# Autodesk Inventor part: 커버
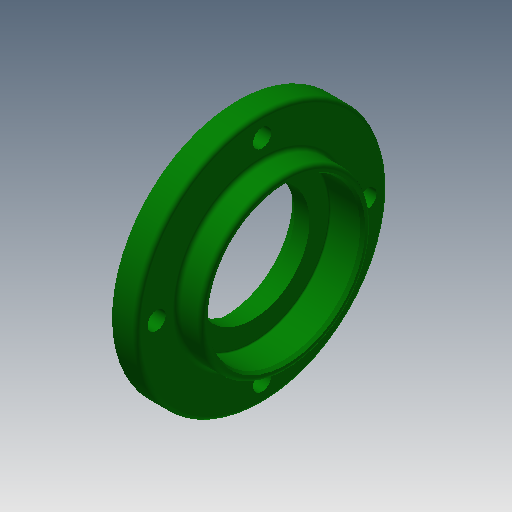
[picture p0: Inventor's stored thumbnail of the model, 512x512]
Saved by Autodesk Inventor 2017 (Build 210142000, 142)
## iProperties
Created: 2018-11
Part Number: 커버
Material: 알루미늄 6061
Document SubType Name: Modeling
Designer: mduedu
Density: 1 g/cm^3
Appearance: Dark Green
Author: mduedu
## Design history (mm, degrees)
sketch "스케치1"
  geometry: L1 (0, 0)-(3, 0); L2 (3, 0)-(3, 20); L3 (3, 20)-(0, 20); L4 (0, 20)-(0, 0); L5 (3, 0)-(9, 0); L6 (9, 0)-(9, 31); L7 (9, 31)-(3, 31); L8 (3, 31)-(3, 0); L9 (9, 0)-(15, 0); L10 (15, 0)-(15, 21); L11 (15, 21)-(9, 21); L12 (9, 21)-(9, 0)
  constraints: 24 end point, 6 parallel, 3 horizontal, 3 perpendicular
  dimensions: "d0" = 62 diameter of L7 L5; "d2" = 42 diameter of L11 L9; "d3" = 40 diameter of L3 L1; "d4" = 3 distance of L2.end L3.end; "d5" = 6 distance of L6.end L7.end; "d6" = 15 distance between parallel lines of L10 L4
revolve "회전1" sketch "스케치1" stored, may be unused: angle "d7" = 90 deg
sketch "스케치2"
  geometry: L1 (0, -20)-(0, 20) reference; L2 (0, 20)-(3, 20) reference; L3 (3, 20)-(3, 31) reference; L4 (3, 31)-(9, 31) reference; L5 (9, 31)-(9, 21) reference; L6 (9, 21)-(15, 21) reference; L7 (15, 21)-(15, -21) reference; L8 (15, -21)-(9, -21) reference; L9 (9, -21)-(9, -31) reference; L10 (9, -31)-(3, -31) reference; L11 (3, -31)-(3, -20) reference; L12 (3, -20)-(0, -20) reference; L13 (0, 0)-(3, 0); L14 (3, 0)-(3, 16.5); L15 (3, 16.5)-(0, 16.5); L16 (0, 16.5)-(0, 0); L17 (3, 0)-(6.7, 0); L18 (6.7, 0)-(6.7, 14); L19 (6.7, 14)-(3, 14); L20 (3, 14)-(3, 0); L21 (6.7, 0)-(15, 0); L22 (15, 0)-(15, 19); L23 (15, 19)-(6.7, 19); L24 (6.7, 19)-(6.7, 0)
  constraints: 24 end point, 6 parallel, 3 horizontal, 3 perpendicular, 1 point on line
  dimensions: "d8" = 38 diameter of L23 L21; "d10" = 28 diameter of L19 L17; "d11" = 33 diameter of L15 L13; "d12" = 3 distance of L14.end L15.end; "d13" = 8.3 distance of L22.end L23.end
revolve "회전2" sketch "스케치2" stored, may be unused: angle "d14" = 90 deg
fillet "모깎기1" dims "d15" = 0.3
chamfer "모따기1" distance "d16" = 0.8; stored, may be unused: second distance "d17" = 2, angle "d18" = 30 deg
fillet "모깎기2" dims "d19" = 1
chamfer "모따기2" distance "d20" = 0.5; stored, may be unused: second distance "d21" = 2, angle "d22" = 30 deg
sketch "스케치3" dims "d23" = 52
  geometry: 6 further points
  constraints: 2 vertical alignment, 1 coincident, 7 other
  dimensions: "d26" = 360 deg dimension on point (0, 0) point (0, 26) (derived)
sketch "스케치4"
  geometry: 4 further points
  constraints: 4 other
hole "구멍1" sketch "스케치4" at (-26, 0), (0, -26), (26, 0), (0, 26) diameter "d28" = 4.5; stored, may be unused: countersink angle "d32" = 90 deg, drill point angle "d34" = 0 deg; dims "d29" = 6, "d30" = 8, "d31" = 4.6, "d33" = 8
node "솔리드1"
node "절단 모서리 투영1"
